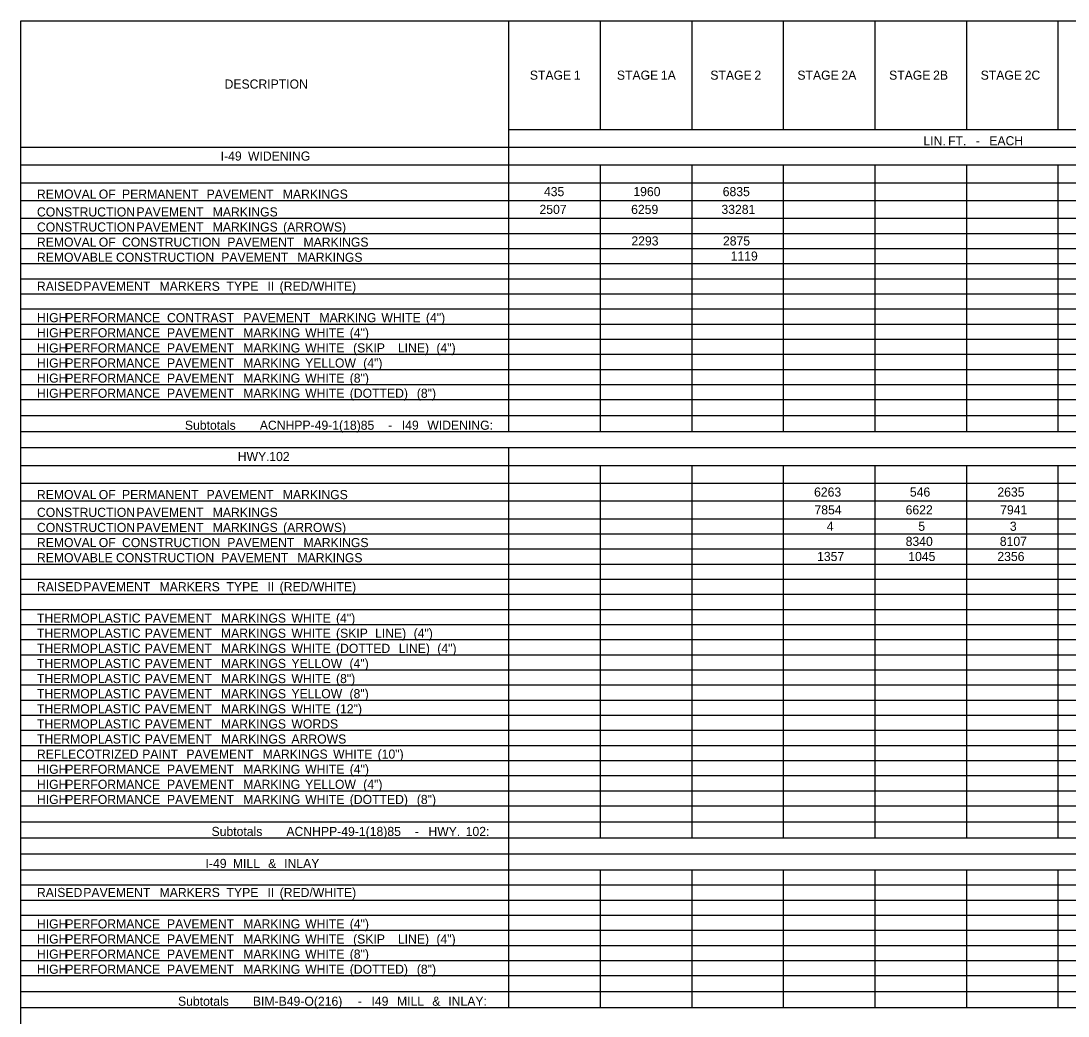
# Model space of a CAD drawing. Extents: x 1225909 to 1228704, y 151309 to 152305.
# Drawn here: x 1226577.4 to 1226949.3, y 151561.1 to 151914.5 of the extents above; entities that cross this region are included whole.
import ezdxf

# ---------------------------------------------------------------- set-up
doc = ezdxf.new("R2010")
doc.units = 0
doc.layers.add('R_Dimension', color=7, linetype='Continuous')

msp = doc.modelspace()

# ---------------------------------------------------------------- linework, layer by layer
at = {"layer": 'R_Dimension'}
for p, q in [((1226577.42, 151914.54), (1228151.92, 151914.54)), ((1226577.42, 151385.44), (1226577.42, 151914.54)), ((1226750.73, 151768.69), (1226750.73, 151914.54)), ((1226783.25, 151876.02), (1226783.25, 151914.54)), ((1226815.77, 151876.02), (1226815.77, 151914.54)), ((1226848.28, 151876.02), (1226848.28, 151914.54)), ((1226880.8, 151876.02), (1226880.8, 151914.54)), ((1226913.31, 151876.02), (1226913.31, 151914.54)), ((1226945.83, 151876.02), (1226945.83, 151914.54)), ((1226750.73, 151876.02), (1228151.92, 151876.02)), ((1226577.42, 151869.71), (1228151.92, 151869.71)), ((1226577.42, 151863.4), (1228151.92, 151863.4)), ((1226783.25, 151768.69), (1226783.25, 151863.4)), ((1226815.77, 151768.69), (1226815.77, 151863.4)), ((1226848.28, 151768.69), (1226848.28, 151863.4)), ((1226880.8, 151768.69), (1226880.8, 151863.4)), ((1226913.31, 151768.69), (1226913.31, 151863.4)), ((1226945.83, 151768.69), (1226945.83, 151863.4)), ((1226577.42, 151857.08), (1228151.92, 151857.08)), ((1226577.42, 151850.77), (1228151.92, 151850.77)), ((1226577.42, 151844.45), (1228151.92, 151844.45)), ((1226577.42, 151839.09), (1228151.92, 151839.09)), ((1226577.42, 151833.72), (1228151.92, 151833.72)), ((1226577.42, 151828.35), (1228151.92, 151828.35)), ((1226577.42, 151822.99), (1228151.92, 151822.99)), ((1226577.42, 151817.62), (1228151.92, 151817.62)), ((1226577.42, 151812.25), (1228151.92, 151812.25)), ((1226577.42, 151806.89), (1228151.92, 151806.89)), ((1226577.42, 151801.52), (1228151.92, 151801.52)), ((1226577.42, 151796.15), (1228151.92, 151796.15)), ((1226577.42, 151790.79), (1228151.92, 151790.79)), ((1226577.42, 151785.42), (1228151.92, 151785.42)), ((1226577.42, 151780.05), (1228151.92, 151780.05)), ((1226577.42, 151774.37), (1228151.92, 151774.37)), ((1226577.42, 151768.69), (1228151.92, 151768.69)), ((1226577.42, 151763.01), (1228151.92, 151763.01)), ((1226750.73, 151564.12), (1226750.73, 151763.01)), ((1226577.42, 151756.69), (1228151.92, 151756.69)), ((1226783.25, 151624.42), (1226783.25, 151756.69)), ((1226815.77, 151624.42), (1226815.77, 151756.69)), ((1226848.28, 151624.42), (1226848.28, 151756.69)), ((1226880.8, 151624.42), (1226880.8, 151756.69)), ((1226913.31, 151624.42), (1226913.31, 151756.69)), ((1226945.83, 151624.42), (1226945.83, 151756.69)), ((1226577.42, 151750.38), (1228151.92, 151750.38)), ((1226577.42, 151744.07), (1228151.92, 151744.07)), ((1226577.42, 151737.75), (1228151.92, 151737.75)), ((1226577.42, 151732.39), (1228151.92, 151732.39)), ((1226577.42, 151727.02), (1228151.92, 151727.02)), ((1226577.42, 151721.65), (1228151.92, 151721.65)), ((1226577.42, 151716.29), (1228151.92, 151716.29)), ((1226577.42, 151710.92), (1228151.92, 151710.92)), ((1226577.42, 151705.55), (1228151.92, 151705.55)), ((1226577.42, 151700.18), (1228151.92, 151700.18)), ((1226577.42, 151694.82), (1228151.92, 151694.82)), ((1226577.42, 151689.45), (1228151.92, 151689.45)), ((1226577.42, 151684.08), (1228151.92, 151684.08)), ((1226577.42, 151678.72), (1228151.92, 151678.72)), ((1226577.42, 151673.35), (1228151.92, 151673.35)), ((1226577.42, 151667.98), (1228151.92, 151667.98)), ((1226577.42, 151662.62), (1228151.92, 151662.62)), ((1226577.42, 151657.25), (1228151.92, 151657.25)), ((1226577.42, 151651.88), (1228151.92, 151651.88)), ((1226577.42, 151646.52), (1228151.92, 151646.52)), ((1226577.42, 151641.15), (1228151.92, 151641.15)), ((1226577.42, 151635.78), (1228151.92, 151635.78)), ((1226577.42, 151630.1), (1228151.92, 151630.1)), ((1226577.42, 151624.42), (1228151.92, 151624.42)), ((1226577.42, 151618.74), (1228151.92, 151618.74)), ((1226577.42, 151613.05), (1228151.92, 151613.05)), ((1226783.25, 151564.12), (1226783.25, 151613.05)), ((1226815.77, 151564.12), (1226815.77, 151613.05)), ((1226848.28, 151564.12), (1226848.28, 151613.05)), ((1226880.8, 151564.12), (1226880.8, 151613.05)), ((1226913.31, 151564.12), (1226913.31, 151613.05)), ((1226945.83, 151564.12), (1226945.83, 151613.05)), ((1226577.42, 151607.69), (1228151.92, 151607.69)), ((1226577.42, 151602.32), (1228151.92, 151602.32)), ((1226577.42, 151596.95), (1228151.92, 151596.95)), ((1226577.42, 151591.59), (1228151.92, 151591.59)), ((1226577.42, 151586.22), (1228151.92, 151586.22)), ((1226577.42, 151580.85), (1228151.92, 151580.85)), ((1226577.42, 151575.49), (1228151.92, 151575.49)), ((1226577.42, 151569.81), (1228151.92, 151569.81)), ((1226577.42, 151564.12), (1228151.92, 151564.12))]:
    msp.add_line(p, q, dxfattribs=at)

# ---------------------------------------------------------------- texts
for s, height, p in [('STAGE', 3.238, (1226758.16, 151893.66)), (' 1', 3.238, (1226772.59, 151893.66)), ('STAGE', 3.238, (1226789.08, 151893.66)), (' 1A', 3.238, (1226803.51, 151893.66)), ('STAGE', 3.238, (1226822.27, 151893.66)), (' 2', 3.238, (1226836.7, 151893.66)), ('STAGE', 3.238, (1226853.19, 151893.66)), (' 2A', 3.238, (1226867.62, 151893.66)), ('STAGE', 3.238, (1226885.76, 151893.66)), (' 2B', 3.238, (1226900.19, 151893.66)), ('STAGE', 3.238, (1226918.28, 151893.66)), (' 2C', 3.238, (1226932.71, 151893.66)), ('DESCRIPTION', 3.2378, (1226649.74, 151890.51)), ('LIN.', 3.238, (1226897.96, 151870.36)), (' FT.', 3.238, (1226905.51, 151870.36)), (' EACH', 3.238, (1226920.14, 151870.36)), (' -', 3.238, (1226915.33, 151870.36)), ('I-49', 3.238, (1226648.36, 151864.93)), (' WIDENING', 3.238, (1226656.85, 151864.93)), ('REMOVAL', 3.238, (1226583.1, 151851.42)), (' OF', 3.238, (1226603.86, 151851.42)), (' PERMANENT', 3.238, (1226612.12, 151851.42)), (' PAVEMENT', 3.238, (1226642.15, 151851.42)), (' MARKINGS', 3.238, (1226669.22, 151851.42)), ('435', 3.238, (1226763.17, 151852.31)), ('1960', 3.238, (1226794.93, 151852.31)), ('6835', 3.238, (1226826.67, 151852.31)), ('CONSTRUCTION', 3.2378, (1226583.1, 151845.1)), (' PAVEMENT', 3.238, (1226617.24, 151845.1)), (' MARKINGS', 3.238, (1226644.32, 151845.1)), ('2507', 3.238, (1226761.59, 151845.99)), ('6259', 3.238, (1226794.14, 151845.99)), ('33281', 3.238, (1226826.21, 151845.99)), (' (ARROWS)', 3.238, (1226669.33, 151839.74)), ('CONSTRUCTION', 3.2378, (1226583.1, 151839.74)), (' PAVEMENT', 3.238, (1226617.24, 151839.74)), (' MARKINGS', 3.238, (1226644.32, 151839.74)), ('REMOVAL', 3.238, (1226583.1, 151834.37)), (' OF', 3.238, (1226603.86, 151834.37)), (' CONSTRUCTION', 3.2378, (1226612.12, 151834.37)), (' PAVEMENT', 3.238, (1226649.49, 151834.37)), (' MARKINGS', 3.238, (1226676.57, 151834.37)), ('2293', 3.238, (1226794.23, 151834.79)), ('2875', 3.238, (1226826.75, 151834.79)), ('REMOVABLE', 3.238, (1226583.1, 151829)), (' CONSTRUCTION', 3.2378, (1226609.97, 151829)), (' PAVEMENT', 3.238, (1226647.35, 151829)), (' MARKINGS', 3.238, (1226674.43, 151829)), ('1119', 3.238, (1226829.49, 151829.42)), ('RAISED', 3.238, (1226583.1, 151818.69)), (' PAVEMENT', 3.238, (1226598.37, 151818.69)), (' MARKERS', 3.238, (1226625.45, 151818.69)), (' TYPE', 3.238, (1226649.24, 151818.69)), (' II', 3.238, (1226663.79, 151818.69)), (' (RED/WHITE)', 3.2378, (1226668.1, 151818.69)), ('HIGH', 3.238, (1226583.1, 151807.54)), (' PERFORMANCE', 3.2378, (1226591.97, 151807.54)), (' CONTRAST', 3.238, (1226628.1, 151807.54)), (' PAVEMENT', 3.238, (1226655.18, 151807.54)), (' MARKING', 3.238, (1226682.25, 151807.54)), (' WHITE', 3.238, (1226704.23, 151807.54)), (' (4")', 3.238, (1226720.06, 151807.54)), ('HIGH', 3.238, (1226583.1, 151802.17)), (' PERFORMANCE', 3.2378, (1226591.97, 151802.17)), (' PAVEMENT', 3.238, (1226628.1, 151802.17)), (' MARKING', 3.238, (1226655.18, 151802.17)), (' WHITE', 3.238, (1226677.15, 151802.17)), (' (4")', 3.238, (1226692.99, 151802.17)), ('HIGH', 3.238, (1226583.1, 151796.8)), (' PERFORMANCE', 3.2378, (1226591.97, 151796.8)), (' PAVEMENT', 3.238, (1226628.1, 151796.8)), (' MARKING', 3.238, (1226655.18, 151796.8)), (' WHITE', 3.238, (1226677.15, 151796.8)), ('  (SKIP', 3.238, (1226692.99, 151796.8)), (' LINE)', 3.238, (1226710.09, 151796.8)), (' (4")', 3.238, (1226723.78, 151796.8)), (' (4")', 3.238, (1226697.78, 151791.44)), ('HIGH', 3.238, (1226583.1, 151791.44)), (' PERFORMANCE', 3.2378, (1226591.97, 151791.44)), (' PAVEMENT', 3.238, (1226628.1, 151791.44)), (' MARKING', 3.238, (1226655.18, 151791.44)), (' YELLOW', 3.238, (1226677.15, 151791.44)), ('HIGH', 3.238, (1226583.1, 151786.07)), (' PERFORMANCE', 3.2378, (1226591.97, 151786.07)), (' PAVEMENT', 3.238, (1226628.1, 151786.07)), (' MARKING', 3.238, (1226655.18, 151786.07)), (' WHITE', 3.238, (1226677.15, 151786.07)), (' (8")', 3.238, (1226692.99, 151786.07)), ('HIGH', 3.238, (1226583.1, 151780.7)), (' PERFORMANCE', 3.2378, (1226591.97, 151780.7)), (' PAVEMENT', 3.238, (1226628.1, 151780.7)), (' MARKING', 3.238, (1226655.18, 151780.7)), (' WHITE', 3.238, (1226677.15, 151780.7)), (' (DOTTED)', 3.238, (1226692.99, 151780.7)), (' (8")', 3.238, (1226716.82, 151780.7)), ('Subtotals', 3.238, (1226635.65, 151769.34)), (' ACNHPP-49-1(18)85', 3.2378, (1226661.05, 151769.34)), (' I49', 3.238, (1226711.47, 151769.34)), (' WIDENING:', 3.238, (1226720.55, 151769.34)), (' -', 3.238, (1226706.66, 151769.34)), ('HWY.', 3.238, (1226654.43, 151758.23)), (' 102', 3.238, (1226664.42, 151758.23)), ('REMOVAL', 3.238, (1226583.1, 151744.71)), (' OF', 3.238, (1226603.86, 151744.71)), (' PERMANENT', 3.238, (1226612.12, 151744.71)), (' PAVEMENT', 3.238, (1226642.15, 151744.71)), (' MARKINGS', 3.238, (1226669.22, 151744.71)), ('6263', 3.238, (1226859.11, 151745.6)), ('546', 3.238, (1226893.14, 151745.6)), ('2635', 3.238, (1226924.22, 151745.6)), ('CONSTRUCTION', 3.2378, (1226583.1, 151738.4)), (' PAVEMENT', 3.238, (1226617.24, 151738.4)), (' MARKINGS', 3.238, (1226644.32, 151738.4)), ('7854', 3.238, (1226859.26, 151739.29)), ('6622', 3.238, (1226891.63, 151739.29)), ('7941', 3.238, (1226925.21, 151739.29)), ('CONSTRUCTION', 3.2378, (1226583.1, 151733.03)), (' PAVEMENT', 3.238, (1226617.24, 151733.03)), (' MARKINGS', 3.238, (1226644.32, 151733.03)), (' (ARROWS)', 3.238, (1226669.33, 151733.03)), ('4', 3.24, (1226863.62, 151733.45)), ('5', 3.24, (1226896.14, 151733.45)), ('3', 3.24, (1226928.65, 151733.45)), ('REMOVAL', 3.238, (1226583.1, 151727.67)), (' OF', 3.238, (1226603.86, 151727.67)), (' CONSTRUCTION', 3.2378, (1226612.12, 151727.67)), (' PAVEMENT', 3.238, (1226649.49, 151727.67)), (' MARKINGS', 3.238, (1226676.57, 151727.67)), ('8340', 3.238, (1226891.64, 151728.08)), ('8107', 3.238, (1226925.08, 151728.08)), ('REMOVABLE', 3.238, (1226583.1, 151722.3)), (' CONSTRUCTION', 3.2378, (1226609.97, 151722.3)), (' PAVEMENT', 3.238, (1226647.35, 151722.3)), (' MARKINGS', 3.238, (1226674.43, 151722.3)), ('1357', 3.238, (1226860.18, 151722.72)), ('1045', 3.238, (1226892.57, 151722.72)), ('2356', 3.238, (1226924.21, 151722.72)), ('RAISED', 3.238, (1226583.1, 151711.98)), (' PAVEMENT', 3.238, (1226598.37, 151711.98)), (' MARKERS', 3.238, (1226625.45, 151711.98)), (' TYPE', 3.238, (1226649.24, 151711.98)), (' II', 3.238, (1226663.79, 151711.98)), (' (RED/WHITE)', 3.2378, (1226668.1, 151711.98)), ('THERMOPLASTIC', 3.2378, (1226583.1, 151700.83)), (' PAVEMENT', 3.238, (1226620.2, 151700.83)), (' MARKINGS', 3.238, (1226647.27, 151700.83)), (' WHITE', 3.238, (1226672.28, 151700.83)), (' (4")', 3.238, (1226688.12, 151700.83)), ('THERMOPLASTIC', 3.2378, (1226583.1, 151695.47)), (' PAVEMENT', 3.238, (1226620.2, 151695.47)), (' MARKINGS', 3.238, (1226647.27, 151695.47)), (' WHITE', 3.238, (1226672.28, 151695.47)), (' (SKIP', 3.238, (1226688.12, 151695.47)), (' LINE)', 3.238, (1226701.98, 151695.47)), (' (4")', 3.238, (1226715.68, 151695.47)), ('THERMOPLASTIC', 3.2378, (1226583.1, 151690.1)), (' PAVEMENT', 3.238, (1226620.2, 151690.1)), (' MARKINGS', 3.238, (1226647.27, 151690.1)), (' WHITE', 3.238, (1226672.28, 151690.1)), (' (DOTTED', 3.238, (1226688.12, 151690.1)), (' LINE)', 3.238, (1226710.4, 151690.1)), (' (4")', 3.238, (1226724.09, 151690.1)), ('THERMOPLASTIC', 3.2378, (1226583.1, 151684.73)), (' PAVEMENT', 3.238, (1226620.2, 151684.73)), (' MARKINGS', 3.238, (1226647.27, 151684.73)), (' YELLOW', 3.238, (1226672.28, 151684.73)), (' (4")', 3.238, (1226692.91, 151684.73)), ('THERMOPLASTIC', 3.2378, (1226583.1, 151679.37)), (' PAVEMENT', 3.238, (1226620.2, 151679.37)), (' MARKINGS', 3.238, (1226647.27, 151679.37)), (' WHITE', 3.238, (1226672.28, 151679.37)), (' (8")', 3.238, (1226688.12, 151679.37)), ('THERMOPLASTIC', 3.2378, (1226583.1, 151674)), (' PAVEMENT', 3.238, (1226620.2, 151674)), (' MARKINGS', 3.238, (1226647.27, 151674)), (' YELLOW', 3.238, (1226672.28, 151674)), (' (8")', 3.238, (1226692.91, 151674)), (' (12")', 3.238, (1226688.12, 151668.63)), ('THERMOPLASTIC', 3.2378, (1226583.1, 151668.63)), (' PAVEMENT', 3.238, (1226620.2, 151668.63)), (' MARKINGS', 3.238, (1226647.27, 151668.63)), (' WHITE', 3.238, (1226672.28, 151668.63)), ('THERMOPLASTIC', 3.2378, (1226583.1, 151663.27)), (' PAVEMENT', 3.238, (1226620.2, 151663.27)), (' MARKINGS', 3.238, (1226647.27, 151663.27)), (' WORDS', 3.238, (1226672.28, 151663.27)), ('THERMOPLASTIC', 3.2378, (1226583.1, 151657.9)), (' PAVEMENT', 3.238, (1226620.2, 151657.9)), (' MARKINGS', 3.238, (1226647.27, 151657.9)), (' ARROWS', 3.238, (1226672.28, 151657.9)), ('REFLECOTRIZED', 3.2378, (1226583.1, 151652.53)), (' PAINT', 3.238, (1226619.28, 151652.53)), (' PAVEMENT', 3.238, (1226634.98, 151652.53)), (' MARKINGS', 3.238, (1226662.06, 151652.53)), (' WHITE', 3.238, (1226687.07, 151652.53)), (' (10")', 3.238, (1226702.9, 151652.53)), ('HIGH', 3.238, (1226583.1, 151647.17)), (' PERFORMANCE', 3.2378, (1226591.97, 151647.17)), (' PAVEMENT', 3.238, (1226628.1, 151647.17)), (' MARKING', 3.238, (1226655.18, 151647.17)), (' WHITE', 3.238, (1226677.15, 151647.17)), (' (4")', 3.238, (1226692.99, 151647.17)), ('HIGH', 3.238, (1226583.1, 151641.8)), (' PERFORMANCE', 3.2378, (1226591.97, 151641.8)), (' PAVEMENT', 3.238, (1226628.1, 151641.8)), (' MARKING', 3.238, (1226655.18, 151641.8)), (' YELLOW', 3.238, (1226677.15, 151641.8)), (' (4")', 3.238, (1226697.78, 151641.8)), ('HIGH', 3.238, (1226583.1, 151636.43)), (' PERFORMANCE', 3.2378, (1226591.97, 151636.43)), (' PAVEMENT', 3.238, (1226628.1, 151636.43)), (' MARKING', 3.238, (1226655.18, 151636.43)), (' WHITE', 3.238, (1226677.15, 151636.43)), (' (DOTTED)', 3.238, (1226692.99, 151636.43)), (' (8")', 3.238, (1226716.82, 151636.43)), ('Subtotals', 3.238, (1226645.11, 151625.07)), (' ACNHPP-49-1(18)85', 3.2378, (1226670.5, 151625.07)), (' HWY.', 3.238, (1226720.93, 151625.07)), (' 102:', 3.238, (1226734.17, 151625.07)), (' -', 3.238, (1226716.11, 151625.07)), ('I-49', 3.238, (1226642.99, 151613.7)), (' MILL', 3.238, (1226651.48, 151613.7)), (' &', 3.238, (1226664, 151613.7)), (' INLAY', 3.238, (1226669.69, 151613.7)), ('RAISED', 3.238, (1226583.1, 151603.39)), (' PAVEMENT', 3.238, (1226598.37, 151603.39)), (' MARKERS', 3.238, (1226625.45, 151603.39)), (' TYPE', 3.238, (1226649.24, 151603.39)), (' II', 3.238, (1226663.79, 151603.39)), (' (RED/WHITE)', 3.2378, (1226668.1, 151603.39)), ('HIGH', 3.238, (1226583.1, 151592.24)), (' PERFORMANCE', 3.2378, (1226591.97, 151592.24)), (' PAVEMENT', 3.238, (1226628.1, 151592.24)), (' MARKING', 3.238, (1226655.18, 151592.24)), (' WHITE', 3.238, (1226677.15, 151592.24)), (' (4")', 3.238, (1226692.99, 151592.24)), ('  (SKIP', 3.238, (1226692.99, 151586.87)), (' LINE)', 3.238, (1226710.09, 151586.87)), (' (4")', 3.238, (1226723.78, 151586.87)), ('HIGH', 3.238, (1226583.1, 151586.87)), (' PERFORMANCE', 3.2378, (1226591.97, 151586.87)), (' PAVEMENT', 3.238, (1226628.1, 151586.87)), (' MARKING', 3.238, (1226655.18, 151586.87)), (' WHITE', 3.238, (1226677.15, 151586.87)), ('HIGH', 3.238, (1226583.1, 151581.5)), (' PERFORMANCE', 3.2378, (1226591.97, 151581.5)), (' PAVEMENT', 3.238, (1226628.1, 151581.5)), (' MARKING', 3.238, (1226655.18, 151581.5)), (' WHITE', 3.238, (1226677.15, 151581.5)), (' (8")', 3.238, (1226692.99, 151581.5)), ('HIGH', 3.238, (1226583.1, 151576.14)), (' PERFORMANCE', 3.2378, (1226591.97, 151576.14)), (' PAVEMENT', 3.238, (1226628.1, 151576.14)), (' MARKING', 3.238, (1226655.18, 151576.14)), (' WHITE', 3.238, (1226677.15, 151576.14)), (' (DOTTED)', 3.238, (1226692.99, 151576.14)), (' (8")', 3.238, (1226716.82, 151576.14)), ('Subtotals', 3.238, (1226633.21, 151564.77)), (' BIM-B49-O(216)', 3.2378, (1226658.6, 151564.77)), (' I49', 3.238, (1226700.72, 151564.77)), (' MILL', 3.238, (1226709.79, 151564.77)), (' &', 3.238, (1226722.31, 151564.77)), (' INLAY:', 3.238, (1226728, 151564.77)), (' -', 3.238, (1226695.9, 151564.77))]:
    msp.add_text(s, height=height, dxfattribs=at).set_placement(p)

doc.saveas('drawing.dxf')
